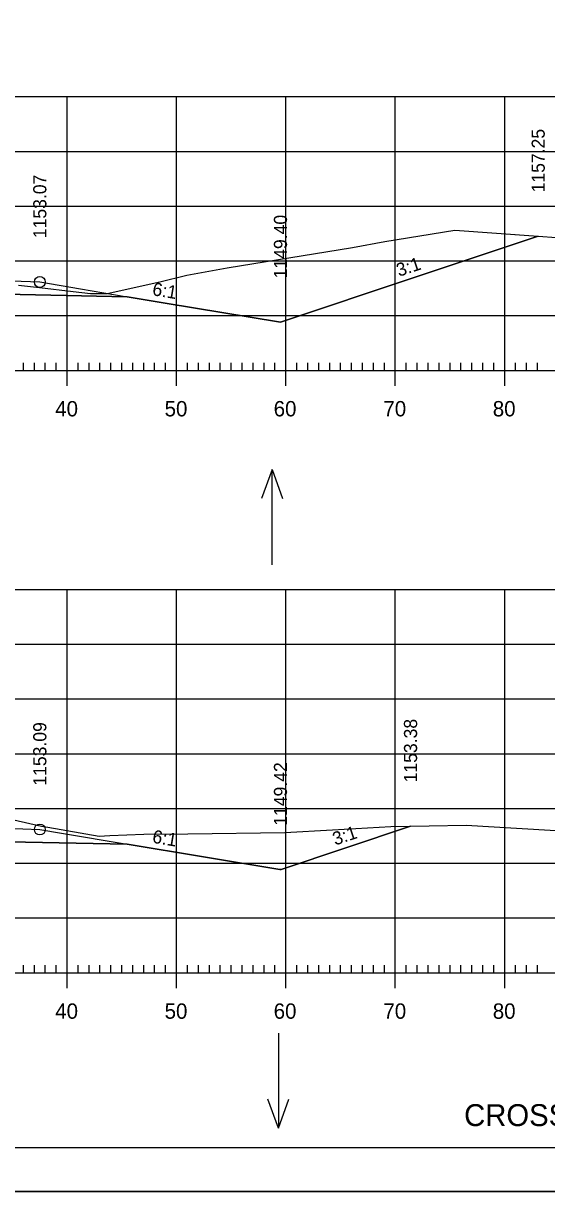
# Model space of a CAD drawing. Extents: x 1322838 to 1324533, y 339903 to 351025.
# Drawn here: x 1323739.7 to 1323787.6, y 341396.5 to 341503.2 of the extents above; entities that cross this region are included whole.
import ezdxf

# ---------------------------------------------------------------- set-up
doc = ezdxf.new("R2010")
doc.units = 0
for name, color, linetype in [('R_Alt Surface', 7, 'Continuous'), ('R_Axis', 7, 'Continuous'), ('R_Axis Annot', 7, 'Continuous'), ('R_Border', 7, 'Continuous'), ('R_Draft', 7, 'Continuous'), ('R_Exist Surface', 7, 'Continuous'), ('R_Fin Surface', 7, 'Continuous'), ('R_Fin Surface Annot', 7, 'Continuous'), ('R_Grid', 7, 'Continuous'), ('R_No Plot', 7, 'Continuous'), ('R_Water Annot', 7, 'Continuous')]:
    doc.layers.add(name, color=color, linetype=linetype)

msp = doc.modelspace()

# ---------------------------------------------------------------- linework, layer by layer
at = {"layer": 'R_Alt Surface'}
for points in [[(1323658.22, 341478.2), (1323672.22, 341478.48), (1323703.72, 341478.91), (1323735.22, 341478.48), (1323749.21, 341478.2)], [(1323658.22, 341428.22), (1323672.22, 341428.5), (1323703.72, 341428.92), (1323735.22, 341428.5), (1323749.21, 341428.22)]]:
    msp.add_lwpolyline(points, dxfattribs=at)
at = {"layer": 'R_Axis'}
for p, q in [((1323743.72, 341470.07), (1323743.72, 341472.87)), ((1323753.72, 341470.07), (1323753.72, 341472.87)), ((1323763.72, 341470.07), (1323763.72, 341472.87)), ((1323773.72, 341470.07), (1323773.72, 341472.87)), ((1323783.72, 341470.07), (1323783.72, 341472.87)), ((1323563.72, 341471.47), (1323843.72, 341471.47)), ((1323739.72, 341471.47), (1323739.72, 341472.17)), ((1323740.72, 341471.47), (1323740.72, 341472.17)), ((1323741.72, 341471.47), (1323741.72, 341472.17)), ((1323742.72, 341471.47), (1323742.72, 341472.17)), ((1323744.72, 341471.47), (1323744.72, 341472.17)), ((1323745.72, 341471.47), (1323745.72, 341472.17)), ((1323746.72, 341471.47), (1323746.72, 341472.17)), ((1323747.72, 341471.47), (1323747.72, 341472.17)), ((1323748.72, 341471.47), (1323748.72, 341472.17)), ((1323749.72, 341471.47), (1323749.72, 341472.17)), ((1323750.72, 341471.47), (1323750.72, 341472.17)), ((1323751.72, 341471.47), (1323751.72, 341472.17)), ((1323752.72, 341471.47), (1323752.72, 341472.17)), ((1323754.72, 341471.47), (1323754.72, 341472.17)), ((1323755.72, 341471.47), (1323755.72, 341472.17)), ((1323756.72, 341471.47), (1323756.72, 341472.17)), ((1323757.72, 341471.47), (1323757.72, 341472.17)), ((1323758.72, 341471.47), (1323758.72, 341472.17)), ((1323759.72, 341471.47), (1323759.72, 341472.17)), ((1323760.72, 341471.47), (1323760.72, 341472.17)), ((1323761.72, 341471.47), (1323761.72, 341472.17)), ((1323762.72, 341471.47), (1323762.72, 341472.17)), ((1323764.72, 341471.47), (1323764.72, 341472.17)), ((1323765.72, 341471.47), (1323765.72, 341472.17)), ((1323766.72, 341471.47), (1323766.72, 341472.17)), ((1323767.72, 341471.47), (1323767.72, 341472.17)), ((1323768.72, 341471.47), (1323768.72, 341472.17)), ((1323769.72, 341471.47), (1323769.72, 341472.17)), ((1323770.72, 341471.47), (1323770.72, 341472.17)), ((1323771.72, 341471.47), (1323771.72, 341472.17)), ((1323772.72, 341471.47), (1323772.72, 341472.17)), ((1323774.72, 341471.47), (1323774.72, 341472.17)), ((1323775.72, 341471.47), (1323775.72, 341472.17)), ((1323776.72, 341471.47), (1323776.72, 341472.17)), ((1323777.72, 341471.47), (1323777.72, 341472.17)), ((1323778.72, 341471.47), (1323778.72, 341472.17)), ((1323779.72, 341471.47), (1323779.72, 341472.17)), ((1323780.72, 341471.47), (1323780.72, 341472.17)), ((1323781.72, 341471.47), (1323781.72, 341472.17)), ((1323782.72, 341471.47), (1323782.72, 341472.17)), ((1323784.72, 341471.47), (1323784.72, 341472.17)), ((1323785.72, 341471.47), (1323785.72, 341472.17)), ((1323786.72, 341471.47), (1323786.72, 341472.17)), ((1323739.72, 341416.47), (1323739.72, 341417.17)), ((1323740.72, 341416.47), (1323740.72, 341417.17)), ((1323741.72, 341416.47), (1323741.72, 341417.17)), ((1323742.72, 341416.47), (1323742.72, 341417.17)), ((1323743.72, 341415.07), (1323743.72, 341417.87)), ((1323744.72, 341416.47), (1323744.72, 341417.17)), ((1323745.72, 341416.47), (1323745.72, 341417.17)), ((1323746.72, 341416.47), (1323746.72, 341417.17)), ((1323747.72, 341416.47), (1323747.72, 341417.17)), ((1323748.72, 341416.47), (1323748.72, 341417.17)), ((1323749.72, 341416.47), (1323749.72, 341417.17)), ((1323750.72, 341416.47), (1323750.72, 341417.17)), ((1323751.72, 341416.47), (1323751.72, 341417.17)), ((1323752.72, 341416.47), (1323752.72, 341417.17)), ((1323753.72, 341415.07), (1323753.72, 341417.87)), ((1323754.72, 341416.47), (1323754.72, 341417.17)), ((1323755.72, 341416.47), (1323755.72, 341417.17)), ((1323756.72, 341416.47), (1323756.72, 341417.17)), ((1323757.72, 341416.47), (1323757.72, 341417.17)), ((1323758.72, 341416.47), (1323758.72, 341417.17)), ((1323759.72, 341416.47), (1323759.72, 341417.17)), ((1323760.72, 341416.47), (1323760.72, 341417.17)), ((1323761.72, 341416.47), (1323761.72, 341417.17)), ((1323762.72, 341416.47), (1323762.72, 341417.17)), ((1323763.72, 341415.07), (1323763.72, 341417.87)), ((1323764.72, 341416.47), (1323764.72, 341417.17)), ((1323765.72, 341416.47), (1323765.72, 341417.17)), ((1323766.72, 341416.47), (1323766.72, 341417.17)), ((1323767.72, 341416.47), (1323767.72, 341417.17)), ((1323768.72, 341416.47), (1323768.72, 341417.17)), ((1323769.72, 341416.47), (1323769.72, 341417.17)), ((1323770.72, 341416.47), (1323770.72, 341417.17)), ((1323771.72, 341416.47), (1323771.72, 341417.17)), ((1323772.72, 341416.47), (1323772.72, 341417.17)), ((1323773.72, 341415.07), (1323773.72, 341417.87)), ((1323774.72, 341416.47), (1323774.72, 341417.17)), ((1323775.72, 341416.47), (1323775.72, 341417.17)), ((1323776.72, 341416.47), (1323776.72, 341417.17)), ((1323777.72, 341416.47), (1323777.72, 341417.17)), ((1323778.72, 341416.47), (1323778.72, 341417.17)), ((1323779.72, 341416.47), (1323779.72, 341417.17)), ((1323780.72, 341416.47), (1323780.72, 341417.17)), ((1323781.72, 341416.47), (1323781.72, 341417.17)), ((1323782.72, 341416.47), (1323782.72, 341417.17)), ((1323783.72, 341415.07), (1323783.72, 341417.87)), ((1323784.72, 341416.47), (1323784.72, 341417.17)), ((1323785.72, 341416.47), (1323785.72, 341417.17)), ((1323786.72, 341416.47), (1323786.72, 341417.17)), ((1323563.72, 341416.47), (1323843.72, 341416.47))]:
    msp.add_line(p, q, dxfattribs=at)
at = {"layer": 'R_Border'}
msp.add_line((1323861.9, 341400.47), (1323545.72, 341400.47), dxfattribs=at)
at = {"layer": 'R_Exist Surface'}
for points in [[(1323739.28, 341479.26), (1323741.18, 341479.03), (1323744.26, 341478.68), (1323745.84, 341478.5), (1323746.74, 341478.49), (1323747.39, 341478.49), (1323752.19, 341479.54), (1323754.67, 341480.15), (1323758.35, 341480.82), (1323769.81, 341482.69), (1323772.77, 341483.25), (1323779.17, 341484.26), (1323796.08, 341483.07)], [(1323737.77, 341430.68), (1323741.39, 341429.85), (1323741.95, 341429.75), (1323746.65, 341428.95), (1323747.63, 341428.99), (1323750.73, 341429.12), (1323754.76, 341429.14), (1323763.61, 341429.28), (1323767.99, 341429.53), (1323773.3, 341429.81), (1323776.82, 341429.9), (1323780.19, 341429.96), (1323822.18, 341427.44)]]:
    msp.add_lwpolyline(points, dxfattribs=at)
at = {"layer": 'R_Fin Surface'}
for points in [[(1323607.85, 341487.99), (1323626.65, 341481.72), (1323644.22, 341475.87), (1323649.14, 341476.69), (1323658.22, 341478.2), (1323666.22, 341479.54), (1323667.27, 341479.58), (1323672.22, 341479.78), (1323674.22, 341479.82), (1323692.76, 341480.19), (1323703.72, 341480.41), (1323733.22, 341479.82), (1323735.22, 341479.78), (1323741.22, 341479.54), (1323744.94, 341478.92), (1323749.21, 341478.2), (1323752.69, 341477.62), (1323763.22, 341475.87), (1323775.53, 341479.97), (1323786.78, 341483.72)], [(1323597.09, 341441.6), (1323597.09, 341441.59), (1323644.22, 341425.89), (1323657.29, 341428.07), (1323658.22, 341428.22), (1323666.22, 341429.55), (1323668.39, 341429.64), (1323672.22, 341429.79), (1323674.22, 341429.83), (1323695.85, 341430.27), (1323703.72, 341430.42), (1323733.22, 341429.83), (1323733.28, 341429.83), (1323735.22, 341429.79), (1323738.12, 341429.68), (1323741.22, 341429.55), (1323743.21, 341429.22), (1323749.21, 341428.22), (1323763.17, 341425.89), (1323763.22, 341425.89), (1323763.27, 341425.9), (1323775.11, 341429.85)]]:
    msp.add_lwpolyline(points, dxfattribs=at)
at = {"layer": 'R_Grid'}
for p, q in [((1323563.72, 341496.47), (1323843.72, 341496.47)), ((1323743.72, 341471.47), (1323743.72, 341496.47)), ((1323753.72, 341471.47), (1323753.72, 341496.47)), ((1323763.72, 341471.47), (1323763.72, 341496.47)), ((1323773.72, 341471.47), (1323773.72, 341496.47)), ((1323783.72, 341471.47), (1323783.72, 341496.47)), ((1323563.72, 341491.47), (1323843.72, 341491.47)), ((1323563.72, 341486.47), (1323843.72, 341486.47)), ((1323563.72, 341481.47), (1323843.72, 341481.47)), ((1323563.72, 341476.47), (1323843.72, 341476.47)), ((1323563.72, 341471.47), (1323843.72, 341471.47)), ((1323563.72, 341451.47), (1323843.72, 341451.47)), ((1323743.72, 341416.47), (1323743.72, 341451.47)), ((1323753.72, 341416.47), (1323753.72, 341451.47)), ((1323763.72, 341416.47), (1323763.72, 341451.47)), ((1323773.72, 341416.47), (1323773.72, 341451.47)), ((1323783.72, 341416.47), (1323783.72, 341451.47)), ((1323563.72, 341446.47), (1323843.72, 341446.47)), ((1323563.72, 341441.47), (1323843.72, 341441.47)), ((1323563.72, 341436.47), (1323843.72, 341436.47)), ((1323563.72, 341431.47), (1323843.72, 341431.47)), ((1323563.72, 341426.47), (1323843.72, 341426.47)), ((1323563.72, 341421.47), (1323843.72, 341421.47)), ((1323563.72, 341416.47), (1323843.72, 341416.47))]:
    msp.add_line(p, q, dxfattribs=at)
at = {"layer": 'R_No Plot'}
msp.add_line((1323533.31, 341396.49), (1323866.65, 341396.49), dxfattribs=at)
for points in [[(1323533.31, 341609.82), (1323866.65, 341609.82), (1323866.65, 341396.49), (1323533.31, 341396.49)], [(1323779.64, 341605.93), (1323799.26, 341605.93), (1323799.26, 341596.05), (1323815.37, 341596.05), (1323838.57, 341596.05), (1323838.57, 341563.38), (1323861.77, 341563.38), (1323861.9, 341400.47), (1323545.72, 341400.47), (1323545.72, 341605.93)]]:
    msp.add_lwpolyline(points, close=True, dxfattribs=at)
for points in [[(1323739.28, 341479.26), (1323741.18, 341479.03), (1323744.26, 341478.68), (1323745.84, 341478.5), (1323746.74, 341478.49), (1323747.39, 341478.49), (1323752.19, 341479.54), (1323754.67, 341480.15), (1323758.35, 341480.82), (1323769.81, 341482.69), (1323772.77, 341483.25), (1323779.17, 341484.26), (1323786.78, 341483.72), (1323775.53, 341479.97), (1323763.22, 341475.87), (1323752.69, 341477.62), (1323749.21, 341478.2), (1323735.22, 341478.48)], [(1323737.77, 341430.68), (1323741.39, 341429.85), (1323741.95, 341429.75), (1323746.65, 341428.95), (1323747.63, 341428.99), (1323750.73, 341429.12), (1323754.76, 341429.14), (1323763.61, 341429.28), (1323767.99, 341429.53), (1323773.3, 341429.81), (1323775.11, 341429.85), (1323763.27, 341425.9), (1323763.22, 341425.89), (1323763.17, 341425.89), (1323749.21, 341428.22), (1323735.22, 341428.5)]]:
    msp.add_lwpolyline(points, dxfattribs=at)
for centre in [(1323741.22, 341479.54), (1323741.22, 341479.54), (1323741.22, 341429.55), (1323741.22, 341429.55)]:
    msp.add_circle(centre, 0.5, dxfattribs=at)
at = {"layer": 'R_Water Annot'}
for p, q in [((1323762.45, 341462.42), (1323761.48, 341459.76)), ((1323762.45, 341453.73), (1323762.45, 341462.42)), ((1323762.45, 341462.42), (1323763.42, 341459.76)), ((1323763.04, 341410.96), (1323763.04, 341402.27)), ((1323763.04, 341402.27), (1323762.07, 341404.93)), ((1323763.04, 341402.27), (1323764, 341404.93))]:
    msp.add_line(p, q, dxfattribs=at)

# ---------------------------------------------------------------- texts
at = {"layer": 'R_Axis Annot'}
for s, p in [('40', (1323742.63, 341467.27)), ('50', (1323752.63, 341467.27)), ('60', (1323762.6, 341467.27)), ('70', (1323772.63, 341467.27)), ('80', (1323782.63, 341467.27)), ('40', (1323742.63, 341412.27)), ('50', (1323752.63, 341412.27)), ('60', (1323762.6, 341412.27)), ('70', (1323772.63, 341412.27)), ('80', (1323782.63, 341412.27))]:
    msp.add_text(s, height=1.4, dxfattribs=at).set_placement(p)
at = {"layer": 'R_Draft'}
msp.add_text('CROSS SECTION STA. 125+00 TO STA. 127+00', height=2, dxfattribs=at).set_placement((1323780.01, 341402.47))
at = {"layer": 'R_Fin Surface Annot'}
for s, rotation, p in [('1157.25', 90, (1323787.38, 341487.72)), ('1153.07', 90, (1323741.82, 341483.54)), ('1149.40', 90, (1323763.82, 341479.87)), ('3:1', 18.4342, (1323774.05, 341480.01)), ('6:1', 350.5369, (1323751.45, 341478.34)), ('1153.38', 90, (1323775.71, 341433.85)), ('1153.09', 90, (1323741.82, 341433.55)), ('1149.42', 90, (1323763.82, 341429.89)), ('3:1', 18.4349, (1323768.22, 341428.08)), ('6:1', 350.5369, (1323751.45, 341428.35))]:
    msp.add_text(s, height=1.2, rotation=rotation, dxfattribs=at).set_placement(p)

doc.saveas('drawing.dxf')
